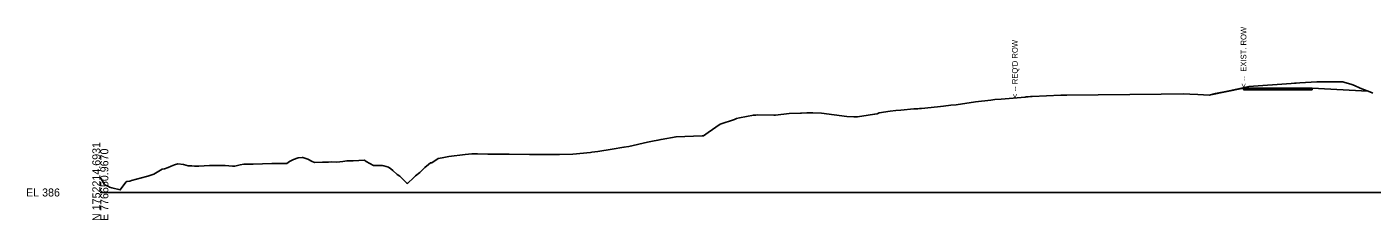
# Model space of a CAD drawing. Extents: x 776426 to 854588, y 1736205 to 1756790.
# Drawn here: x 805845.1 to 806315.8, y 1751705.1 to 1751772.8 of the extents above; entities that cross this region are included whole.
import ezdxf

# ---------------------------------------------------------------- set-up
doc = ezdxf.new("R2010")
doc.units = 0
for name, color, linetype in [('DTM CONTOURS_MAJOR_TX', 7, 'Continuous'), ('DTM_X_FLOW_ARROWS', 7, 'Continuous'), ('XS_P_DR_GRAVEL', 7, 'Continuous'), ('XS_P_GROUND', 7, 'Continuous'), ('XS_P_ROW', 7, 'Continuous'), ('XS_X_ROW', 7, 'Continuous')]:
    doc.layers.add(name, color=color, linetype=linetype)

msp = doc.modelspace()

# ---------------------------------------------------------------- linework, layer by layer
at = {"layer": 'DTM CONTOURS_MAJOR_TX'}
msp.add_line((805870.79, 1751714.76), (806370.79, 1751714.76), dxfattribs=at)
at = {"layer": 'DTM_X_FLOW_ARROWS'}
msp.add_lwpolyline([(805870.79, 1751719.78), (805871.13, 1751719.6), (805872.25, 1751717.57), (805872.59, 1751717.35), (805873.63, 1751716.86), (805874.04, 1751716.57), (805874.79, 1751716.42), (805877.77, 1751715.64), (805879.68, 1751718.4), (805880.11, 1751718.57), (805881.07, 1751718.77), (805881.74, 1751718.95), (805886.98, 1751720.33), (805887.42, 1751720.49), (805889.54, 1751721.17), (805892.43, 1751722.89), (805893.3, 1751723.02), (805894.52, 1751723.48), (805895.57, 1751723.98), (805896.76, 1751724.41), (805897.94, 1751724.75), (805899.87, 1751724.53), (805901.55, 1751724.15), (805902.84, 1751724.07), (805903.69, 1751723.93), (805904.09, 1751723.97), (805905.27, 1751723.95), (805908.96, 1751724.2), (805909.67, 1751724.18), (805911.47, 1751724.21), (805914.09, 1751724.21), (805914.47, 1751724.17), (805917.05, 1751723.98), (805917.89, 1751724), (805919.75, 1751724.42), (805921.01, 1751724.64), (805922.54, 1751724.65), (805924.23, 1751724.68), (805930.79, 1751724.86), (805932.38, 1751724.92), (805935.38, 1751724.91), (805935.99, 1751724.94), (805936.98, 1751725.63), (805938.36, 1751726.27), (805940.05, 1751726.96), (805941.37, 1751727.06), (805941.7, 1751726.97), (805943.38, 1751726.46), (805944.88, 1751725.66), (805945.48, 1751725.4), (805945.86, 1751725.28), (805948.47, 1751725.34), (805950.68, 1751725.37), (805951.51, 1751725.48), (805953.54, 1751725.4), (805954.54, 1751725.5), (805955.69, 1751725.61), (805957.06, 1751725.83), (805959.27, 1751725.89), (805963.18, 1751726.12), (805963.75, 1751725.61), (805966.33, 1751724.23), (805969.52, 1751724.22), (805970.04, 1751724.15), (805971.61, 1751723.61), (805972.39, 1751723.04), (805973.11, 1751722.44), (805974.71, 1751721.04), (805975.58, 1751720.44), (805978.05, 1751717.99), (805978.3, 1751717.93), (805980.46, 1751719.99), (805981.03, 1751720.58), (805982.59, 1751721.77), (805984.39, 1751723.51), (805985.63, 1751724.53), (805986.34, 1751725.12), (805986.76, 1751725.12), (805988.94, 1751726.69), (805990.39, 1751726.93), (805992.72, 1751727.34), (805998.46, 1751728.02), (806000.82, 1751728.25), (806002.8, 1751728.28), (806006.41, 1751728.21), (806010.01, 1751728.18), (806013.84, 1751728.22), (806020.91, 1751728.13), (806022.62, 1751728.12), (806031.49, 1751728.12), (806036.09, 1751728.16), (806042.31, 1751728.77), (806042.79, 1751728.84), (806044.91, 1751729.11), (806049.83, 1751729.93), (806053.99, 1751730.61), (806055.74, 1751730.93), (806062.27, 1751732.45), (806064.05, 1751732.77), (806065.9, 1751733.06), (806067.01, 1751733.37), (806072.23, 1751734.28), (806081.4, 1751734.57), (806081.82, 1751734.6), (806083.52, 1751735.78), (806087.7, 1751738.73), (806092.72, 1751740.39), (806093.38, 1751740.63), (806094.44, 1751740.87), (806099.31, 1751741.89), (806100.12, 1751741.88), (806100.74, 1751741.92), (806106.49, 1751741.87), (806107.07, 1751741.89), (806111.85, 1751742.45), (806115.73, 1751742.59), (806116.14, 1751742.61), (806117.99, 1751742.72), (806118.45, 1751742.72), (806118.99, 1751742.73), (806120.05, 1751742.71), (806123.07, 1751742.57), (806131.95, 1751741.4), (806134.41, 1751741.33), (806135.7, 1751741.25), (806139.46, 1751741.84), (806141.67, 1751742.18), (806142.57, 1751742.36), (806143.29, 1751742.63), (806147.17, 1751743.24), (806149.12, 1751743.44), (806150.86, 1751743.6), (806155.38, 1751744.05), (806156.84, 1751744.13), (806157.43, 1751744.18), (806158.14, 1751744.25), (806163.76, 1751744.83), (806165.76, 1751745.05), (806168.4, 1751745.32), (806170.22, 1751745.45), (806177.03, 1751746.49), (806182.39, 1751747.15), (806183.77, 1751747.3), (806185.95, 1751747.42), (806193.01, 1751748.08), (806194.33, 1751748.2), (806194.75, 1751748.24), (806195.38, 1751748.31), (806196.23, 1751748.36), (806196.89, 1751748.39), (806206.92, 1751748.81), (806208.54, 1751748.87), (806208.92, 1751748.88), (806241.98, 1751749.23), (806249.7, 1751749.29), (806252.04, 1751749.18), (806254.85, 1751749.07), (806258.79, 1751748.9), (806260.99, 1751749.4), (806265.71, 1751750.4), (806272.15, 1751751.78), (806272.62, 1751751.86), (806287.51, 1751752.96), (806288.68, 1751753.05), (806289.26, 1751753.1), (806290.49, 1751753.18), (806296.41, 1751753.55), (806298.35, 1751753.59), (806305.56, 1751753.53), (806305.93, 1751753.45), (806308.7, 1751752.62), (806309.59, 1751752.24), (806311.61, 1751751.36), (806315.56, 1751749.81), (806316.08, 1751749.61)], dxfattribs=at)
at = {"layer": 'XS_P_DR_GRAVEL'}
for points in [[(806282.79, 1751751.29), (806282.79, 1751750.79), (806270.79, 1751750.79), (806270.79, 1751751.29), (806282.79, 1751751.29)], [(806282.79, 1751751.29), (806282.79, 1751750.79), (806294.79, 1751750.79), (806294.79, 1751751.29), (806282.79, 1751751.29)]]:
    msp.add_lwpolyline(points, dxfattribs=at)
at = {"layer": 'XS_P_GROUND'}
for points in [[(806258.79, 1751748.9), (806270.79, 1751751.29)], [(806294.79, 1751751.29), (806314.27, 1751750.32)]]:
    msp.add_lwpolyline(points, dxfattribs=at)

# ---------------------------------------------------------------- texts
at = {"layer": 'DTM CONTOURS_MAJOR_TX'}
for s, p in [('N 1752214.6931', (805870.79, 1751704.76)), ('E 776650.9670', (805873.59, 1751704.76))]:
    msp.add_text(s, height=2.8, rotation=90, dxfattribs=at).set_placement(p)
msp.add_text('EL 386', height=2.8, dxfattribs=at).set_placement((805844.79, 1751713.36))
at = {"layer": 'XS_P_ROW'}
msp.add_text("< -- REQ'D ROW", height=2, rotation=90, dxfattribs=at).set_placement((806191.79, 1751747.88))
at = {"layer": 'XS_X_ROW'}
msp.add_text('< --  EXIST. ROW', height=2, rotation=90, dxfattribs=at).set_placement((806271.79, 1751751.49))

doc.saveas('drawing.dxf')
